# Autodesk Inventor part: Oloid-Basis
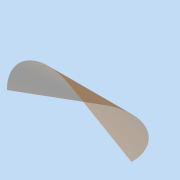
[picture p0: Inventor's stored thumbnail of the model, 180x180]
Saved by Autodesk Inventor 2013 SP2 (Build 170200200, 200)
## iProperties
Created: 2014-11
Part Number: Oloid-Basis
Material: Allgemein
Document SubType Name: Modeling
Designer: Besitzer
Density: 1 g/cm^3
Author: Besitzer
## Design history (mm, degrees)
sketch "Skizze1"
  geometry: L1 (-200, 0)-(0, 0); L2 (0, 0)-(0, 100); L3 (-200, 0)-(267.223, 269.752); A1 r 100 centre (0, 0) between (100, 0) and (-50, 86.603); A2 r 100 centre (0, 0) between (-50, 86.603) and (-50.087, 86.552); 1 further point
  constraints: 6 end point, 5 point on circle, 3 coincident, 2 centre point, 2 point on line, 1 horizontal, 1 perpendicular, 1 tangent
  dimensions: "Radius" = 100 distance of L1.end L2.end; "d6" = 200 distance of L1.start L1.end (= 2 x Radius); "d11" = 0.1 dimension on A2 (= Zugabe)
workpoint "Arbeitspunkt1"
sketch "Skizze2"
  geometry: L1 (100, 0)-(-100, 0); L2 (-100, 0)-(144.975, 141.436); L3 (100, 0)-(100, 100); A1 r 100 centre (100, 0) between (200, 0) and (50, 86.603); A2 r 100 centre (100, 0) between (50, 86.603) and (49.913, 86.552); 1 further point
  constraints: 6 end point, 5 point on circle, 2 centre point, 2 coincident, 2 point on line, 1 horizontal, 1 midpoint, 1 perpendicular, 1 tangent
  dimensions: "d7" = 100 distance of L1.start L3.end (= Radius); "d9" = 100 distance from line of point (0, 0) L3 (= Radius); "d10" = 100 distance of L1.end point (0, 0) (= Radius); "d12" = 0.1 dimension on A2 (= Zugabe)
workpoint "Arbeitspunkt2"
sketch "3D-Skizze1"
feature "Erhabene Fläche2" sketch "3D-Skizze1" dims "d19" = 0, "d20" = 90 deg, "d21" = 0, "d22" = 90 deg, "d23" = 0, "d24" = 90 deg
node "Fläche2"
other parameters: "Zugabe" = 0.1 [user parameter; used in 2 equation terms]
